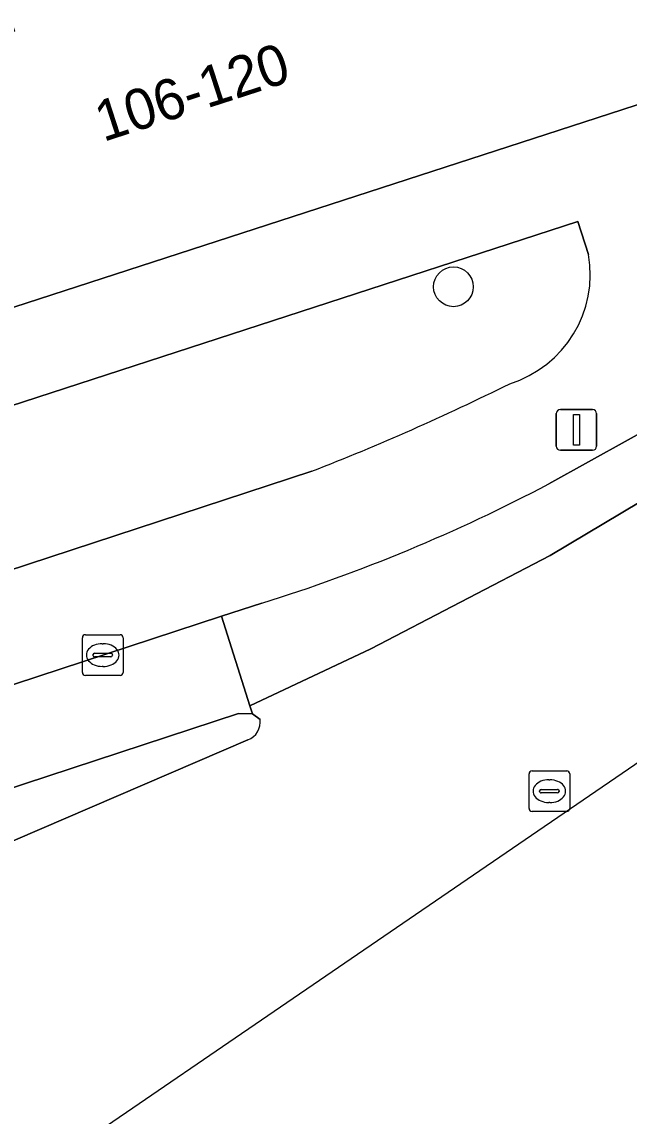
# Model space of a CAD drawing. Extents: x 159371 to 159986, y 382987 to 383597.
# Drawn here: x 159535.58 to 159550.53, y 383013.67 to 383040.59 of the extents above; entities that cross this region are included whole.
import ezdxf

# ---------------------------------------------------------------- set-up
doc = ezdxf.new("R2010")
doc.units = 0
for name, color, linetype in [('IMGEO_Boom', 7, 'Continuous'), ('IMGEO_Fietspad_gesloten', 7, 'Continuous'), ('IMGEO_Fietspad_open', 7, 'Continuous'), ('IMGEO_Groenvoorziening', 7, 'Continuous'), ('IMGEO_Kolk', 7, 'Continuous'), ('IMGEO_Lichtmast', 7, 'Continuous'), ('IMGEO_Pand', 7, 'Continuous'), ('IMGEO_Pand_nummerreeks', 7, 'Continuous'), ('IMGEO_Rijbaan_lokaal_gesloten', 7, 'Continuous'), ('IMGEO_Rioolput', 7, 'Continuous'), ('IMGEO_Verkeerseiland_open', 7, 'Continuous'), ('IMGEO_Voetpad_open', 7, 'Continuous')]:
    doc.layers.add(name, color=color, linetype=linetype)

msp = doc.modelspace()

# ---------------------------------------------------------------- linework, layer by layer
at = {"layer": 'IMGEO_Boom'}
msp.add_circle((159546.204, 383034.072), 0.489, dxfattribs=at)
at = {"layer": 'IMGEO_Fietspad_gesloten'}
for points in [[(159652.535, 383096.746), (159650.734, 383095.571), (159650.457, 383095.252), (159649.93, 383094.821), (159635.946, 383085.684), (159635.738, 383085.549), (159622.718, 383077.077), (159622.562, 383076.976), (159605.98, 383066.198), (159603.885, 383064.847), (159590.552, 383056.229), (159590.351, 383056.099), (159577.935, 383047.992), (159564.424, 383039.242), (159551.484, 383030.846), (159548.555, 383029.223)], [(159541.487, 383026.287), (159540.493, 383025.968), (159541.194, 383023.766), (159544.169, 383025.165), (159548.581, 383027.46), (159553.444, 383030.36), (159557.531, 383032.962), (159608.238, 383065.907), (159653.356, 383095.206)]]:
    msp.add_lwpolyline(points, dxfattribs=at)
msp.add_arc((159528.825, 383066.744), 42.392, 287.3784, 297.7369, dxfattribs=at)
at = {"layer": 'IMGEO_Fietspad_open'}
msp.add_lwpolyline([(159517.801, 383017.1), (159522.727, 383017.61), (159530.342, 383020.109), (159540.912, 383023.577), (159541.258, 383023.564), (159541.194, 383023.766), (159540.493, 383025.968), (159532.565, 383023.369), (159529.522, 383022.407), (159525.835, 383021.197), (159522.923, 383020.434), (159519.978, 383019.792)], dxfattribs=at)
at = {"layer": 'IMGEO_Groenvoorziening'}
for points in [[(159549.53, 383034.869), (159549.268, 383035.678), (159520.608, 383026.365)], [(159520.608, 383026.365), (159521.761, 383022.662), (159542.718, 383029.536)]]:
    msp.add_lwpolyline(points, dxfattribs=at)
for centre, radius, start, end in [((159546.753, 383034.38), 2.82, 287.243, 9.9912), ((159521.719, 383083.679), 58.072, 291.19821, 296.45364)]:
    msp.add_arc(centre, radius, start, end, dxfattribs=at)
at = {"layer": 'IMGEO_Kolk'}
for p, q in [((159537.145, 383025.512), (159537.997, 383025.512)), ((159537.07, 383024.586), (159537.07, 383025.438)), ((159537.558, 383025.292), (159537.583, 383025.292)), ((159538.071, 383025.438), (159538.071, 383024.586)), ((159537.329, 383025.006), (159537.329, 383025.018)), ((159537.372, 383025.055), (159537.77, 383025.055)), ((159537.813, 383025.018), (159537.813, 383025.006)), ((159537.767, 383024.969), (159537.369, 383024.969)), ((159537.581, 383024.732), (159537.556, 383024.732)), ((159537.997, 383024.512), (159537.145, 383024.512))]:
    msp.add_line(p, q, dxfattribs=at)
for points in [[(159537.145, 383025.512), (159537.997, 383025.512)], [(159537.07, 383024.586), (159537.07, 383025.438)], [(159538.071, 383025.438), (159538.071, 383024.586)], [(159537.997, 383024.512), (159537.145, 383024.512)]]:
    msp.add_lwpolyline(points, dxfattribs=at)
for centre, radius, start, end in [((159537.147, 383025.436), 0.0765, 91.552, 178.448), ((159537.147, 383025.436), 0.0765, 91.552, 178.448), ((159537.995, 383025.436), 0.0765, 1.552, 88.448), ((159537.995, 383025.436), 0.0765, 1.552, 88.448), ((159537.369, 383025.015), 0.0403, 85.8775, 175.7526), ((159537.366, 383025.005), 0.0366, 178.938, 274.7102), ((159537.77, 383025.012), 0.043, 264.8664, 352.4533), ((159537.774, 383025.017), 0.0386, 1.7309, 96.639), ((159537.147, 383024.588), 0.0765, 181.552, 268.448), ((159537.147, 383024.588), 0.0765, 181.552, 268.448), ((159537.995, 383024.588), 0.0765, 271.552, 358.448), ((159537.995, 383024.588), 0.0765, 271.552, 358.448)]:
    msp.add_arc(centre, radius, start, end, dxfattribs=at)
for centre, major_axis, ratio, start_param, end_param in [((159537.557, 383025.012), (-0.387, 0.002), 0.722429, 4.712389, 7.853982), ((159537.582, 383025.012), (-0.39, 0.002), 0.717154, 1.570796, 4.712389)]:
    msp.add_ellipse(centre, major_axis=major_axis, ratio=ratio, start_param=start_param, end_param=end_param, dxfattribs=at)
at = {"layer": 'IMGEO_Lichtmast'}
for p, q in [((159548.736, 383030.152), (159548.736, 383030.952)), ((159548.736, 383030.952), (159548.736, 383030.152)), ((159548.836, 383031.052), (159549.626, 383031.052)), ((159549.626, 383031.052), (159548.836, 383031.052)), ((159549.726, 383030.952), (159549.726, 383030.152)), ((159549.726, 383030.152), (159549.726, 383030.952)), ((159549.626, 383030.052), (159548.836, 383030.052)), ((159548.836, 383030.052), (159549.626, 383030.052))]:
    msp.add_line(p, q, dxfattribs=at)
msp.add_lwpolyline([(159549.156, 383030.927), (159549.306, 383030.927), (159549.306, 383030.177), (159549.156, 383030.177), (159549.156, 383030.927)], dxfattribs=at)
for centre, start, end in [((159548.836, 383030.952), 90, 180), ((159548.836, 383030.952), 90, 180), ((159549.626, 383030.952), 0, 90), ((159549.626, 383030.952), 360, 90), ((159548.836, 383030.152), 180, 270), ((159548.836, 383030.152), 180, 270), ((159549.626, 383030.152), 270, 0), ((159549.626, 383030.152), 270, 0)]:
    msp.add_arc(centre, 0.1, start, end, dxfattribs=at)
at = {"layer": 'IMGEO_Pand'}
msp.add_lwpolyline([(159556.336, 383044.392), (159554.984, 383043.971), (159553.469, 383048.633), (159548.4, 383046.987), (159546.693, 383046.432), (159539.322, 383044.039), (159537.609, 383043.482), (159534.692, 383042.535), (159535.4, 383040.357), (159530.588, 383038.795), (159529.6, 383041.839), (159523.019, 383039.702), (159523.976, 383036.575), (159526.049, 383037.247), (159526.758, 383035.059), (159525.407, 383034.621), (159526.629, 383030.733), (159557.552, 383040.764)], close=True, dxfattribs=at)
at = {"layer": 'IMGEO_Rijbaan_lokaal_gesloten'}
for points in [[(159653.356, 383095.206), (159608.238, 383065.907), (159557.531, 383032.962), (159553.444, 383030.36), (159548.581, 383027.46), (159544.169, 383025.165), (159541.194, 383023.766), (159541.258, 383023.564), (159541.443, 383023.43)], [(159527.287, 383008.919), (159526.163, 383008.079), (159526.882, 383006.066), (159552.249, 383023.406), (159552.836, 383023.807), (159553.43, 383024.411), (159558.076, 383028.041), (159577.133, 383040.415)], [(159541.145, 383022.923), (159528.345, 383017.424), (159523.128, 383015.473), (159525.526, 383009.681), (159526.489, 383010.196)]]:
    msp.add_lwpolyline(points, dxfattribs=at)
msp.add_arc((159540.971, 383023.366), 0.476, 291.4032, 7.7052, dxfattribs=at)
at = {"layer": 'IMGEO_Rioolput'}
for p, q in [((159548.064, 383021.238), (159548.064, 383022.09)), ((159548.139, 383022.164), (159548.991, 383022.164)), ((159549.065, 383022.09), (159549.065, 383021.238)), ((159548.552, 383021.944), (159548.577, 383021.944)), ((159548.323, 383021.658), (159548.323, 383021.67)), ((159548.761, 383021.621), (159548.363, 383021.621)), ((159548.366, 383021.707), (159548.764, 383021.707)), ((159548.807, 383021.67), (159548.807, 383021.658)), ((159548.575, 383021.384), (159548.55, 383021.384)), ((159548.991, 383021.164), (159548.139, 383021.164))]:
    msp.add_line(p, q, dxfattribs=at)
for points in [[(159548.064, 383021.238), (159548.064, 383022.09)], [(159548.139, 383022.164), (159548.991, 383022.164)], [(159549.065, 383022.09), (159549.065, 383021.238)], [(159548.991, 383021.164), (159548.139, 383021.164)]]:
    msp.add_lwpolyline(points, dxfattribs=at)
for centre, radius, start, end in [((159548.141, 383022.088), 0.0765, 91.552, 178.448), ((159548.141, 383022.088), 0.0765, 91.552, 178.448), ((159548.989, 383022.088), 0.0765, 1.552, 88.448), ((159548.989, 383022.088), 0.0765, 1.552, 88.448), ((159548.363, 383021.667), 0.0403, 85.8775, 175.7526), ((159548.36, 383021.657), 0.0366, 178.938, 274.7102), ((159548.764, 383021.664), 0.043, 264.8664, 352.4533), ((159548.768, 383021.669), 0.0386, 1.7309, 96.639), ((159548.141, 383021.24), 0.0765, 181.552, 268.448), ((159548.141, 383021.24), 0.0765, 181.552, 268.448), ((159548.989, 383021.24), 0.0765, 271.552, 358.448), ((159548.989, 383021.24), 0.0765, 271.552, 358.448)]:
    msp.add_arc(centre, radius, start, end, dxfattribs=at)
for centre, major_axis, ratio, start_param, end_param in [((159548.551, 383021.664), (-0.387, 0.002), 0.722429, 4.712389, 7.853982), ((159548.576, 383021.664), (-0.39, 0.002), 0.717154, 1.570796, 4.712389)]:
    msp.add_ellipse(centre, major_axis=major_axis, ratio=ratio, start_param=start_param, end_param=end_param, dxfattribs=at)
at = {"layer": 'IMGEO_Verkeerseiland_open'}
for points in [[(159541.443, 383023.43), (159541.258, 383023.564), (159540.912, 383023.577), (159530.342, 383020.109), (159522.727, 383017.61)], [(159522.454, 383017.007), (159523.128, 383015.473), (159528.345, 383017.424), (159541.145, 383022.923)]]:
    msp.add_lwpolyline(points, dxfattribs=at)
msp.add_arc((159540.971, 383023.366), 0.476, 291.4032, 7.7052, dxfattribs=at)
at = {"layer": 'IMGEO_Voetpad_open'}
for points in [[(159651.919, 383103.426), (159644.09, 383096.707), (159604.582, 383071.057), (159600.956, 383068.714), (159559.512, 383041.791), (159557.552, 383040.764), (159526.629, 383030.733), (159524.666, 383030.142), (159519.89, 383028.504), (159517.392, 383027.837), (159515.199, 383027.456), (159512.634, 383027.01), (159510.971, 383026.907), (159511.777, 383025.694), (159513.757, 383022.714), (159514.768, 383021.485)], [(159521.761, 383022.662), (159520.608, 383026.365), (159549.268, 383035.678), (159549.53, 383034.869)], [(159548.555, 383029.223), (159551.484, 383030.846)], [(159542.718, 383029.536), (159521.761, 383022.662)], [(159519.978, 383019.792), (159522.923, 383020.434), (159525.835, 383021.197), (159529.522, 383022.407), (159532.565, 383023.369), (159540.493, 383025.968), (159541.487, 383026.287)]]:
    msp.add_lwpolyline(points, dxfattribs=at)
for centre, radius, start, end in [((159546.753, 383034.38), 2.82, 287.243, 9.9912), ((159521.719, 383083.679), 58.072, 291.19821, 296.45364), ((159528.825, 383066.744), 42.392, 287.3784, 297.7369)]:
    msp.add_arc(centre, radius, start, end, dxfattribs=at)

# ---------------------------------------------------------------- texts
at = {"layer": 'IMGEO_Pand_nummerreeks'}
msp.add_text('106-120', height=1, rotation=17.9508, dxfattribs=at).set_placement((159537.584, 383037.632))

doc.saveas('drawing.dxf')
